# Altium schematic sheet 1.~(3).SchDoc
size 420 x 297 mm
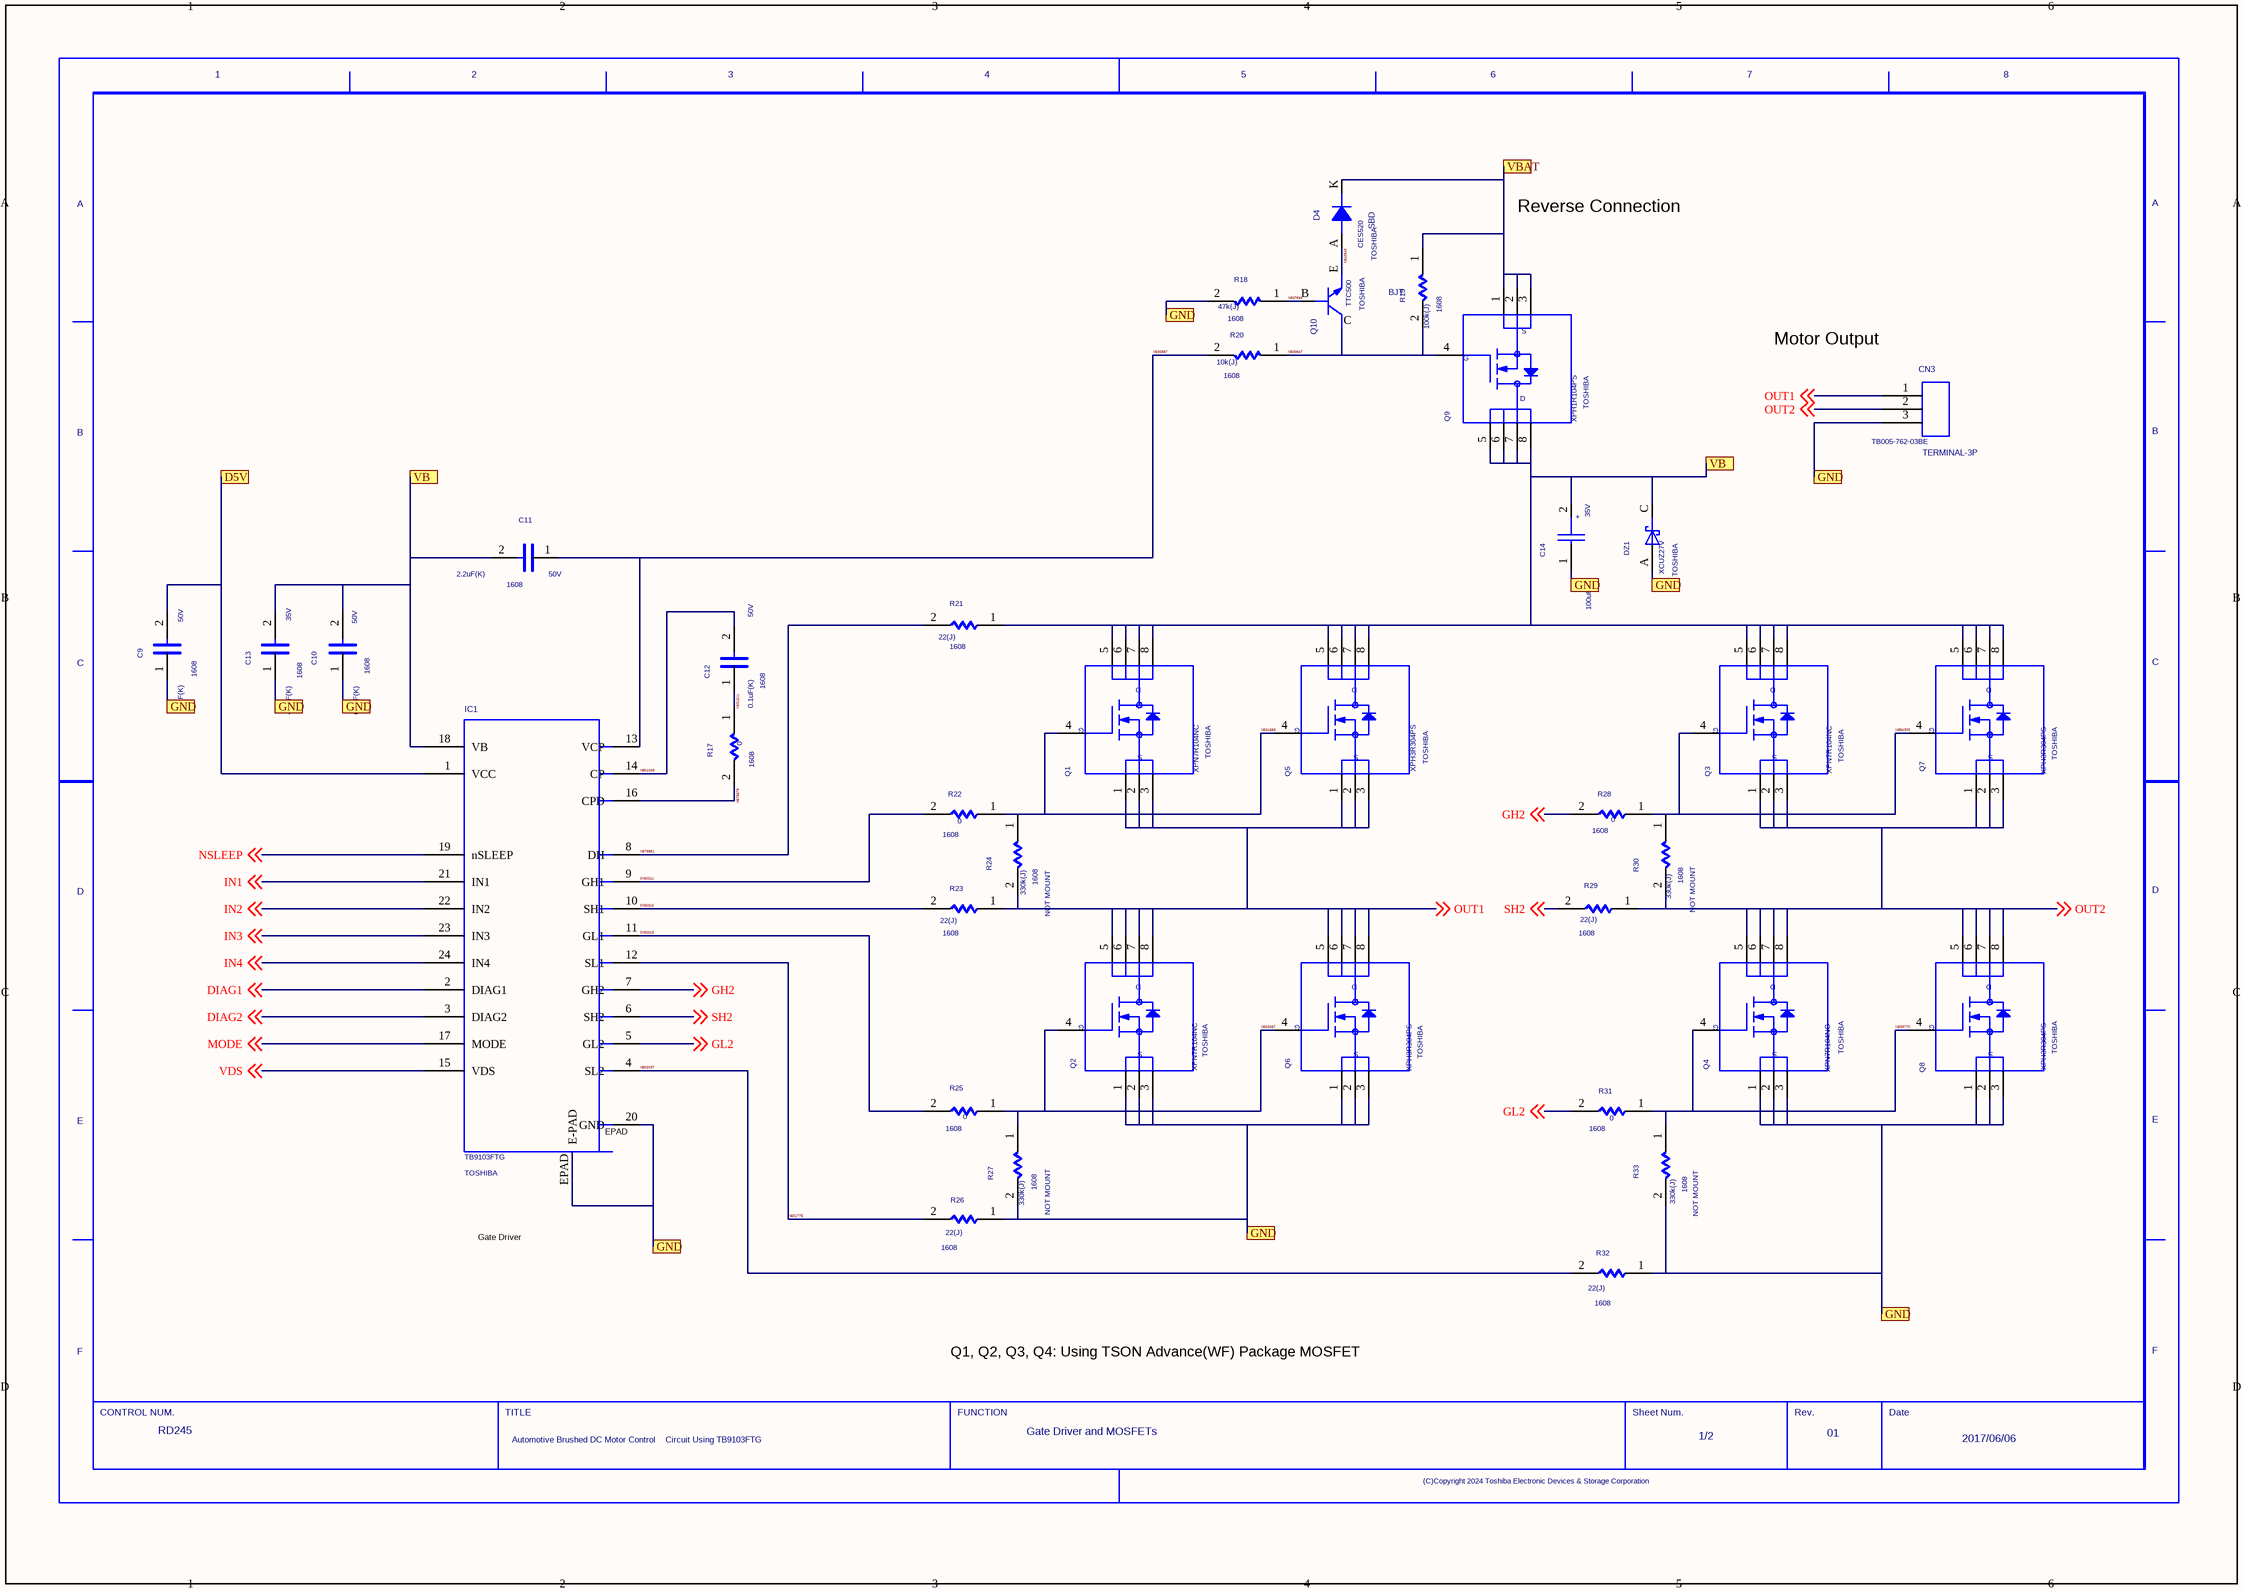
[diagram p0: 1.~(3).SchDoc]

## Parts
C9  SIZECODESMD: 1608  VAL2: 50V  VAL1: 0.1uF(K)  (hidden comment: C)
C10  SIZECODESMD: 1608  VAL2: 50V  VAL1: 0.1uF(K)  (hidden comment: C)
C11  SIZECODESMD: 1608  VAL2: 50V  VAL1: 2.2uF(K)  (hidden comment: C)
C12  SIZECODESMD: 1608  VAL2: 50V  VAL1: 0.1uF(K)  (hidden comment: C)
C13  SIZECODESMD: 1608  VAL2: 35V  VAL1: 4.7uF(K)  (hidden comment: C)
C14  VAL2: 35V  VAL1: 100uF(M)  (hidden comment: CP)
CN3  TERMINAL-3P  VAL3: TB005-762-03BE
D4  SBD  USERCOMPTEXT3: TOSHIBA  VAL3: CES520
DZ1  VAL3: XCUZ27V  USERCOMPTEXT3: TOSHIBA  (hidden comment: SBD)
IC1  USERCOMPTEXT3: TOSHIBA  VAL3: TB9103FTG  (hidden comment: TC241_3)
Q1  VAL3: XPN7R104NC  USERCOMPTEXT3: TOSHIBA  (hidden comment: MFNAC)
Q2  VAL3: XPN7R104NC  USERCOMPTEXT3: TOSHIBA  (hidden comment: MFNAC)
Q3  VAL3: XPN7R104NC  USERCOMPTEXT3: TOSHIBA  (hidden comment: MFNAC)
Q4  VAL3: XPN7R104NC  USERCOMPTEXT3: TOSHIBA  (hidden comment: MFNAC)
Q5  VAL3: XPH3R304PS  USERCOMPTEXT3: TOSHIBA  (hidden comment: MFNAC)
Q6  VAL3: XPH3R304PS  USERCOMPTEXT3: TOSHIBA  (hidden comment: MFNAC)
Q7  VAL3: XPH3R304PS  USERCOMPTEXT3: TOSHIBA  (hidden comment: MFNAC)
Q8  VAL3: XPH3R304PS  USERCOMPTEXT3: TOSHIBA  (hidden comment: MFNAC)
Q9  VAL3: XPH1R104PS  USERCOMPTEXT3: TOSHIBA  (hidden comment: MFNAC)
Q10  BJT  USERCOMPTEXT3: TOSHIBA  VAL3: TTC500
R17  SIZECODESMD: 1608  VAL1: 0  (hidden comment: R)
R18  SIZECODESMD: 1608  VAL1: 47k(J)  (hidden comment: R)
R19  SIZECODESMD: 1608  VAL1: 100k(J)  (hidden comment: R)
R20  SIZECODESMD: 1608  VAL1: 10k(J)  (hidden comment: R)
R21  SIZECODESMD: 1608  VAL1: 22(J)  (hidden comment: R)
R22  SIZECODESMD: 1608  VAL1: 0  (hidden comment: R)
R23  SIZECODESMD: 1608  VAL1: 22(J)  (hidden comment: R)
R24  SIZECODESMD: 1608  VAL1: 330k(J)  NOTMOUNT: NOT MOUNT  (hidden comment: R)
R25  SIZECODESMD: 1608  VAL1: 0  (hidden comment: R)
R26  SIZECODESMD: 1608  VAL1: 22(J)  (hidden comment: R)
R27  SIZECODESMD: 1608  VAL1: 330k(J)  NOTMOUNT: NOT MOUNT  (hidden comment: R)
R28  SIZECODESMD: 1608  VAL1: 0  (hidden comment: R)
R29  SIZECODESMD: 1608  VAL1: 22(J)  (hidden comment: R)
R30  SIZECODESMD: 1608  VAL1: 330k(J)  NOTMOUNT: NOT MOUNT  (hidden comment: R)
R31  SIZECODESMD: 1608  VAL1: 0  (hidden comment: R)
R32  SIZECODESMD: 1608  VAL1: 22(J)  (hidden comment: R)
R33  SIZECODESMD: 1608  VAL1: 330k(J)  NOTMOUNT: NOT MOUNT  (hidden comment: R)
U?  DATE: 2017/06/06  REVISION: 01  FUNCTION: Gate Driver and MOSFETs  DRAWINGNUMBER: RD245  TITLE: Automotive Brushed DC Motor Control / Circuit Using TB9103FTG  SHEETNUMBER: 1/2  (hidden comment: WAKU_DEF100)

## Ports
D5V, GND, VB, VBAT

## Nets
D5V: C9.2 IC1.1(VCC) ; port D5V
DIAG1: IC1.2(DIAG1) ; off-sheet DIAG1
DIAG2: IC1.3(DIAG2) ; off-sheet DIAG2
GH2: IC1.7(GH2) R28.2 ; off-sheet GH2
GL2: IC1.5(GL2) R31.2 ; off-sheet GL2
GND: C9.1 C10.1 C13.1 C14.1 CN3.3 DZ1.A IC1.20(GND) IC1.EPAD(E-PAD) Q2.1 Q2.2 Q2.3 Q4.1 Q4.2 Q4.3 Q6.1 Q6.2 Q6.3 Q8.1 Q8.2 Q8.3 R18.2 R26.1 R27.2 R32.1 R33.2 ; port GND
IN1: IC1.21(IN1) ; off-sheet IN1
IN2: IC1.22(IN2) ; off-sheet IN2
IN3: IC1.23(IN3) ; off-sheet IN3
IN4: IC1.24(IN4) ; off-sheet IN4
MODE: IC1.17(MODE) ; off-sheet MODE
N500947: Q9.4 Q10.C R19.2 R20.1
N500987: C11.1 IC1.13(VCP) R20.2
N501039: C12.2 IC1.14(CP)
N501211: C12.1 R17.1
N501689: Q1.4 Q5.4 R22.1 R24.1
N501775: IC1.12(SL1) R26.2
N502037: IC1.4(SL2) R32.2
N502087: Q2.4 Q6.4 R25.1 R27.1
N533770: Q4.4 Q8.4 R31.1 R33.1
N554303: Q3.4 Q7.4 R28.1 R30.1
N575579: IC1.16(CPD) R17.2
N576851: IC1.8(DH) R21.2
N607694: Q10.B R18.1
N610543: D4.A Q10.E
NSLEEP: IC1.19(nSLEEP) ; off-sheet NSLEEP
OUT1: CN3.1 Q1.1 Q1.2 Q1.3 Q2.5 Q2.6 Q2.7 Q2.8 Q5.1 Q5.2 Q5.3 Q6.5 Q6.6 Q6.7 Q6.8 R23.1 R24.2 ; off-sheet OUT1
OUT2: CN3.2 Q3.1 Q3.2 Q3.3 Q4.5 Q4.6 Q4.7 Q4.8 Q7.1 Q7.2 Q7.3 Q8.5 Q8.6 Q8.7 Q8.8 R29.1 R30.2 ; off-sheet OUT2
SH2: IC1.6(SH2) R29.2 ; off-sheet SH2
SIG0011: IC1.9(GH1) R22.2
SIG0012: IC1.10(SH1) R23.2
SIG0013: IC1.11(GL1) R25.2
VB: C10.2 C11.2 C13.2 C14.2 DZ1.C IC1.18(VB) Q1.5 Q1.6 Q1.7 Q1.8 Q3.5 Q3.6 Q3.7 Q3.8 Q5.5 Q5.6 Q5.7 Q5.8 Q7.5 Q7.6 Q7.7 Q7.8 Q9.5 Q9.6 Q9.7 Q9.8 R21.1 ; port VB
VBAT: D4.K Q9.1 Q9.2 Q9.3 R19.1 ; port VBAT
VDS: IC1.15(VDS) ; off-sheet VDS

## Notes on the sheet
- Reverse Connection
  Protector
- Motor Output
- (near IC1) EPAD
- Gate Driver
- Q1, Q2, Q3, Q4: Using TSON Advance(WF) Package MOSFET
  Q5, Q6, Q7, Q8: Using SOP Advance(WF) Package MOSFET

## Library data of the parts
C9 = C: UPDATETIME: 17:22:43; UPDATEUSER: sptcae13; SAVECOUNT: 1; ORIGINALSYMBOLORIGIN: (0,0); QUADMODEL: CON_10U; FUNCN: C_C; NOMINALCAPACITA: 10u; RATEDVOLTAGE: 25; CDMASTERCADCELG: KC0167; MAKER: TDK; OUMEMAKER: MRT 村田製作所; ADSMODELNAME: s_ZRB18AR61E106ME01L; VAL4: Murata; FNLEADFREETHET1GT2GMCTH1: N_N_N; VAL3: GCM188R71H104KA57J; CAPACITANCETOLE: M; OUMECLASSIFICATION: セラミックコンデンサ; OUMEMAKERKATAMEI: ZRB18AR61E106ME01L; INSTANCENAME: INS530329
C10 = C: UPDATETIME: 17:22:43; UPDATEUSER: sptcae13; SAVECOUNT: 1; ORIGINALSYMBOLORIGIN: (0,0); QUADMODEL: CON_10U; FUNCN: C_C; NOMINALCAPACITA: 10u; RATEDVOLTAGE: 25; CDMASTERCADCELG: KC0167; MAKER: TDK; OUMEMAKER: MRT 村田製作所; ADSMODELNAME: s_ZRB18AR61E106ME01L; VAL4: Murata; FNLEADFREETHET1GT2GMCTH1: N_N_N; VAL3: GCM188R71H104KA57J; CAPACITANCETOLE: M; OUMECLASSIFICATION: セラミックコンデンサ; OUMEMAKERKATAMEI: ZRB18AR61E106ME01L; INSTANCENAME: INS530425
C11 = C: UPDATETIME: 17:22:43; UPDATEUSER: sptcae13; SAVECOUNT: 1; ORIGINALSYMBOLORIGIN: (0,0); QUADMODEL: CON_10U; FUNCN: C_C; NOMINALCAPACITA: 10u; RATEDVOLTAGE: 25; CDMASTERCADCELG: KC0167; MAKER: TDK; OUMEMAKER: MRT 村田製作所; ADSMODELNAME: s_ZRB18AR61E106ME01L; VAL4: Murata; FNLEADFREETHET1GT2GMCTH1: N_N_N; VAL3: GRT188R61H225KE13D; CAPACITANCETOLE: M; OUMECLASSIFICATION: セラミックコンデンサ; OUMEMAKERKATAMEI: ZRB18AR61E106ME01L; INSTANCENAME: INS530173
C12 = C: UPDATETIME: 17:22:43; UPDATEUSER: sptcae13; SAVECOUNT: 1; ORIGINALSYMBOLORIGIN: (0,0); QUADMODEL: CON_10U; FUNCN: C_C; NOMINALCAPACITA: 10u; RATEDVOLTAGE: 25; CDMASTERCADCELG: KC0167; MAKER: TDK; OUMEMAKER: MRT 村田製作所; ADSMODELNAME: s_ZRB18AR61E106ME01L; VAL4: Murata; FNLEADFREETHET1GT2GMCTH1: N_N_N; VAL3: GCM188R71H104KA57J; CAPACITANCETOLE: M; OUMECLASSIFICATION: セラミックコンデンサ; OUMEMAKERKATAMEI: ZRB18AR61E106ME01L; INSTANCENAME: INS529943
C13 = C: UPDATETIME: 17:22:43; UPDATEUSER: sptcae13; SAVECOUNT: 1; ORIGINALSYMBOLORIGIN: (0,0); QUADMODEL: CON_10U; FUNCN: C_C; NOMINALCAPACITA: 10u; RATEDVOLTAGE: 25; CDMASTERCADCELG: KC0167; MAKER: TDK; OUMEMAKER: MRT 村田製作所; ADSMODELNAME: s_ZRB18AR61E106ME01L; VAL4: Murata; FNLEADFREETHET1GT2GMCTH1: N_N_N; VAL3: GRT188R6YA475KE13D; CAPACITANCETOLE: M; OUMECLASSIFICATION: セラミックコンデンサ; OUMEMAKERKATAMEI: ZRB18AR61E106ME01L; INSTANCENAME: INS647841
C14 = CP: OUMEPARTTYPE: C; SAVEAREA0: -1450,-153,20294,13055; UPDATETIME: 16:13:42; UPDATEUSER: fukuda-y; TIME: 15:02:55; SAVECOUNT: 52; ORIGINALSYMBOLORIGIN: (0,0); QUADMODEL: CON_330U; FUNCN: CP_CP; RATEDVOLTAGE: 450; NOMINALCAPACITA: 330u; CDMASTERCADCELG: DC213N; MAKER: RUBYCON; GCOUNT: 1; SIZECODESMD: DIP; OUMEMAKER: SIT ルビコン; VAL4: Chemi-Con; FNLEADFREETHET1GT2GMCTH1: 9_N_N; VAL3: HHXD350ARA101MHA0G; CAPACITANCETOLE: M; OUMECLASSIFICATION: アルミ電解コンデンサ; OUMEMAKERKATAMEI: 450MXC330M35X40; CHIPSIZE: D35xL30; INSTANCENAME: INS636800
CN3 = CON3: SAVECOUNT: 1; UPDATEUSER: sptcae13; UPDATETIME: 09:49:24; OriginalSymbolOrigin: (0,0); FUNCN: CON3_CON3; VAL4: CUI Devices; VAL2: 300V/30A; INSTANCENAME: INS530345
D4 = DIODE_0: SAVECOUNT: 1; UPDATEUSER: sptcae13; UPDATETIME: 09:49:24; OriginalSymbolOrigin: (0,0); FUNCN: DIODE_0_DIODE_0; INSTANCENAME: INS530245
DZ1 = SBD: SAVEAREA0: -4630,-153,17114,13055; UPDATETIME: 08:16:22; UPDATEUSER: fukuda-y; TIME: 14:49:55; SAVECOUNT: 1; ORIGINALSYMBOLORIGIN: (0,0); COMPONENTNAME: SBD_SBD; INSTANCENAME: INS530189
IC1 = TC241_3: SAVECOUNT: 1; UPDATEUSER: sptcae13; UPDATETIME: 09:49:24; OriginalSymbolOrigin: (0,0); FUNCN: TC241_3_Graphic_Schematic_1_package; VAL1: GATE_DRIVER; INSTANCENAME: cmp65
Q1 = MFNAC_23: SAVEAREA0: -10143,-336,37609,28718; UPDATETIME: 14:45:16; UPDATEUSER: 19990028; TIME: 18:29:30; SAVECOUNT: 1; ORIGINALSYMBOLORIGIN: (0,0); COMPONENTNAME: MFNAC_23_MFNAC_23; INSTANCENAME: INS529903
Q2 = MFNAC_23: SAVEAREA0: -10143,-336,37609,28718; UPDATETIME: 14:45:16; UPDATEUSER: 19990028; TIME: 18:29:30; SAVECOUNT: 1; ORIGINALSYMBOLORIGIN: (0,0); COMPONENTNAME: MFNAC_23_MFNAC_23; INSTANCENAME: INS530205
Q3 = MFNAC_23: SAVEAREA0: -10143,-336,37609,28718; UPDATETIME: 14:45:16; UPDATEUSER: 19990028; TIME: 18:29:30; SAVECOUNT: 1; ORIGINALSYMBOLORIGIN: (0,0); COMPONENTNAME: MFNAC_23_MFNAC_23; INSTANCENAME: INS533486
Q4 = MFNAC_23: SAVEAREA0: -10143,-336,37609,28718; UPDATETIME: 14:45:16; UPDATEUSER: 19990028; TIME: 18:29:30; SAVECOUNT: 1; ORIGINALSYMBOLORIGIN: (0,0); COMPONENTNAME: MFNAC_23_MFNAC_23; INSTANCENAME: INS533696
Q5 = MFNAC_23: SAVEAREA0: -10143,-336,37609,28718; UPDATETIME: 14:45:16; UPDATEUSER: 19990028; TIME: 18:29:30; SAVECOUNT: 1; ORIGINALSYMBOLORIGIN: (0,0); COMPONENTNAME: MFNAC_23_MFNAC_23; INSTANCENAME: INS530025
Q6 = MFNAC_23: SAVEAREA0: -10143,-336,37609,28718; UPDATETIME: 14:45:16; UPDATEUSER: 19990028; TIME: 18:29:30; SAVECOUNT: 1; ORIGINALSYMBOLORIGIN: (0,0); COMPONENTNAME: MFNAC_23_MFNAC_23; INSTANCENAME: INS530385
Q7 = MFNAC_23: SAVEAREA0: -10143,-336,37609,28718; UPDATETIME: 14:45:16; UPDATEUSER: 19990028; TIME: 18:29:30; SAVECOUNT: 1; ORIGINALSYMBOLORIGIN: (0,0); COMPONENTNAME: MFNAC_23_MFNAC_23; INSTANCENAME: INS533510
Q8 = MFNAC_23: SAVEAREA0: -10143,-336,37609,28718; UPDATETIME: 14:45:16; UPDATEUSER: 19990028; TIME: 18:29:30; SAVECOUNT: 1; ORIGINALSYMBOLORIGIN: (0,0); COMPONENTNAME: MFNAC_23_MFNAC_23; INSTANCENAME: INS533720
Q9 = MFNAC_23: SAVEAREA0: -10143,-336,37609,28718; UPDATETIME: 14:45:16; UPDATEUSER: 19990028; TIME: 18:29:30; SAVECOUNT: 1; ORIGINALSYMBOLORIGIN: (0,0); COMPONENTNAME: MFNAC_23_MFNAC_23; INSTANCENAME: INS529983
Q10 = 2N1069_0: SAVECOUNT: 1; UPDATEUSER: sptcae13; UPDATETIME: 09:49:24; PSPICETEMPLATE: Q^@REFDES %C %B %E; OriginalSymbolOrigin: (0,5080); FUNCN: 2N1069_0_2N1069_0; INSTANCENAME: INS529959
R17 = R: UPDATETIME: 17:22:43; UPDATEUSER: sptcae13; SAVECOUNT: 1; ORIGINALSYMBOLORIGIN: (0,0); QUADMODEL: RES_1M; FUNCN: R_R; CDMASTERCADCELG: KC0020; MAKER: KOA; RESISTANCETOLER: J; OUMEMAKER: SSM 進工業; POWERRATING: 500m; MOUNTINGFORMSMD: SMD; NOMINALRESISTAN: 1m; ADSMODELNAME: s_RL1632H_R001_JN; FNLEADFREETHET1GT2GMCTH1: N_N_N; VAL3: RK73Z1JTTD; OUMECLASSIFICATION: 表面実装用固定抵抗器; OUMEMAKERKATAMEI: RL1632H-R001-JN; CHIPSIZE: 3216; INSTANCENAME: INS529855
R18 = R: UPDATETIME: 17:22:43; UPDATEUSER: sptcae13; SAVECOUNT: 1; ORIGINALSYMBOLORIGIN: (0,0); QUADMODEL: RES_1M; FUNCN: R_R; CDMASTERCADCELG: KC0020; MAKER: KOA; RESISTANCETOLER: J; OUMEMAKER: SSM 進工業; POWERRATING: 500m; MOUNTINGFORMSMD: SMD; NOMINALRESISTAN: 1m; ADSMODELNAME: s_RL1632H_R001_JN; FNLEADFREETHET1GT2GMCTH1: N_N_N; VAL3: RK73B1JTTD473J; VAL2: 100mW; OUMECLASSIFICATION: 表面実装用固定抵抗器; OUMEMAKERKATAMEI: RL1632H-R001-JN; CHIPSIZE: 3216; INSTANCENAME: INS529871
R19 = R: UPDATETIME: 17:22:43; UPDATEUSER: sptcae13; SAVECOUNT: 1; ORIGINALSYMBOLORIGIN: (0,0); QUADMODEL: RES_1M; FUNCN: R_R; CDMASTERCADCELG: KC0020; MAKER: KOA; RESISTANCETOLER: J; OUMEMAKER: SSM 進工業; POWERRATING: 500m; MOUNTINGFORMSMD: SMD; NOMINALRESISTAN: 1m; ADSMODELNAME: s_RL1632H_R001_JN; FNLEADFREETHET1GT2GMCTH1: N_N_N; VAL3: RK73B1JTTD104J; VAL2: 100mW; OUMECLASSIFICATION: 表面実装用固定抵抗器; OUMEMAKERKATAMEI: RL1632H-R001-JN; CHIPSIZE: 3216; INSTANCENAME: INS530265
R20 = R: UPDATETIME: 17:22:43; UPDATEUSER: sptcae13; SAVECOUNT: 1; ORIGINALSYMBOLORIGIN: (0,0); QUADMODEL: RES_1M; FUNCN: R_R; CDMASTERCADCELG: KC0020; MAKER: KOA; RESISTANCETOLER: J; OUMEMAKER: SSM 進工業; POWERRATING: 500m; MOUNTINGFORMSMD: SMD; NOMINALRESISTAN: 1m; ADSMODELNAME: s_RL1632H_R001_JN; FNLEADFREETHET1GT2GMCTH1: N_N_N; VAL3: RK73B1JTTD103J; VAL2: 100mW; OUMECLASSIFICATION: 表面実装用固定抵抗器; OUMEMAKERKATAMEI: RL1632H-R001-JN; CHIPSIZE: 3216; INSTANCENAME: INS529887
R21 = R: UPDATETIME: 17:22:43; UPDATEUSER: sptcae13; SAVECOUNT: 1; ORIGINALSYMBOLORIGIN: (0,0); QUADMODEL: RES_1M; FUNCN: R_R; CDMASTERCADCELG: KC0020; MAKER: KOA; RESISTANCETOLER: J; OUMEMAKER: SSM 進工業; POWERRATING: 500m; MOUNTINGFORMSMD: SMD; NOMINALRESISTAN: 1m; ADSMODELNAME: s_RL1632H_R001_JN; FNLEADFREETHET1GT2GMCTH1: N_N_N; VAL3: RK73B1JTTD220J; VAL2: 125mW; OUMECLASSIFICATION: 表面実装用固定抵抗器; OUMEMAKERKATAMEI: RL1632H-R001-JN; CHIPSIZE: 3216; INSTANCENAME: INS575614
R22 = R: UPDATETIME: 17:22:43; UPDATEUSER: sptcae13; SAVECOUNT: 1; ORIGINALSYMBOLORIGIN: (0,0); QUADMODEL: RES_1M; FUNCN: R_R; CDMASTERCADCELG: KC0020; MAKER: KOA; RESISTANCETOLER: J; OUMEMAKER: SSM 進工業; POWERRATING: 500m; MOUNTINGFORMSMD: SMD; NOMINALRESISTAN: 1m; ADSMODELNAME: s_RL1632H_R001_JN; FNLEADFREETHET1GT2GMCTH1: N_N_N; VAL3: RK73Z1JTTD; OUMECLASSIFICATION: 表面実装用固定抵抗器; OUMEMAKERKATAMEI: RL1632H-R001-JN; CHIPSIZE: 3216; INSTANCENAME: INS530281
R23 = R: UPDATETIME: 17:22:43; UPDATEUSER: sptcae13; SAVECOUNT: 1; ORIGINALSYMBOLORIGIN: (0,0); QUADMODEL: RES_1M; FUNCN: R_R; CDMASTERCADCELG: KC0020; MAKER: KOA; RESISTANCETOLER: J; OUMEMAKER: SSM 進工業; POWERRATING: 500m; MOUNTINGFORMSMD: SMD; NOMINALRESISTAN: 1m; ADSMODELNAME: s_RL1632H_R001_JN; FNLEADFREETHET1GT2GMCTH1: N_N_N; VAL3: RK73B1JTTD220J; VAL2: 125mW; OUMECLASSIFICATION: 表面実装用固定抵抗器; OUMEMAKERKATAMEI: RL1632H-R001-JN; CHIPSIZE: 3216; INSTANCENAME: INS577102
R24 = R: UPDATETIME: 17:22:43; UPDATEUSER: sptcae13; SAVECOUNT: 1; ORIGINALSYMBOLORIGIN: (0,0); QUADMODEL: RES_1M; FUNCN: R_R; CDMASTERCADCELG: KC0020; MAKER: KOA; RESISTANCETOLER: J; OUMEMAKER: SSM 進工業; POWERRATING: 500m; MOUNTINGFORMSMD: SMD; NOMINALRESISTAN: 1m; ADSMODELNAME: s_RL1632H_R001_JN; FNLEADFREETHET1GT2GMCTH1: N_N_N; VAL3: RK73B1JTTD334J; VAL2: 100mW; OUMECLASSIFICATION: 表面実装用固定抵抗器; OUMEMAKERKATAMEI: RL1632H-R001-JN; CHIPSIZE: 3216; INSTANCENAME: INS586735
R25 = R: UPDATETIME: 17:22:43; UPDATEUSER: sptcae13; SAVECOUNT: 1; ORIGINALSYMBOLORIGIN: (0,0); QUADMODEL: RES_1M; FUNCN: R_R; CDMASTERCADCELG: KC0020; MAKER: KOA; RESISTANCETOLER: J; OUMEMAKER: SSM 進工業; POWERRATING: 500m; MOUNTINGFORMSMD: SMD; NOMINALRESISTAN: 1m; ADSMODELNAME: s_RL1632H_R001_JN; FNLEADFREETHET1GT2GMCTH1: N_N_N; VAL3: RK73Z1JTTD; OUMECLASSIFICATION: 表面実装用固定抵抗器; OUMEMAKERKATAMEI: RL1632H-R001-JN; CHIPSIZE: 3216; INSTANCENAME: INS530297
R26 = R: UPDATETIME: 17:22:43; UPDATEUSER: sptcae13; SAVECOUNT: 1; ORIGINALSYMBOLORIGIN: (0,0); QUADMODEL: RES_1M; FUNCN: R_R; CDMASTERCADCELG: KC0020; MAKER: KOA; RESISTANCETOLER: J; OUMEMAKER: SSM 進工業; POWERRATING: 500m; MOUNTINGFORMSMD: SMD; NOMINALRESISTAN: 1m; ADSMODELNAME: s_RL1632H_R001_JN; FNLEADFREETHET1GT2GMCTH1: N_N_N; VAL3: RK73B1JTTD220J; VAL2: 125mW; OUMECLASSIFICATION: 表面実装用固定抵抗器; OUMEMAKERKATAMEI: RL1632H-R001-JN; CHIPSIZE: 3216; INSTANCENAME: INS577602
R27 = R: UPDATETIME: 17:22:43; UPDATEUSER: sptcae13; SAVECOUNT: 1; ORIGINALSYMBOLORIGIN: (0,0); QUADMODEL: RES_1M; FUNCN: R_R; CDMASTERCADCELG: KC0020; MAKER: KOA; RESISTANCETOLER: J; OUMEMAKER: SSM 進工業; POWERRATING: 500m; MOUNTINGFORMSMD: SMD; NOMINALRESISTAN: 1m; ADSMODELNAME: s_RL1632H_R001_JN; FNLEADFREETHET1GT2GMCTH1: N_N_N; VAL3: RK73B1JTTD334J; VAL2: 100mW; OUMECLASSIFICATION: 表面実装用固定抵抗器; OUMEMAKERKATAMEI: RL1632H-R001-JN; CHIPSIZE: 3216; INSTANCENAME: INS591774
R28 = R: UPDATETIME: 17:22:43; UPDATEUSER: sptcae13; SAVECOUNT: 1; ORIGINALSYMBOLORIGIN: (0,0); QUADMODEL: RES_1M; FUNCN: R_R; CDMASTERCADCELG: KC0020; MAKER: KOA; RESISTANCETOLER: J; OUMEMAKER: SSM 進工業; POWERRATING: 500m; MOUNTINGFORMSMD: SMD; NOMINALRESISTAN: 1m; ADSMODELNAME: s_RL1632H_R001_JN; FNLEADFREETHET1GT2GMCTH1: N_N_N; VAL3: RK73Z1JTTD; OUMECLASSIFICATION: 表面実装用固定抵抗器; OUMEMAKERKATAMEI: RL1632H-R001-JN; CHIPSIZE: 3216; INSTANCENAME: INS533534
R29 = R: UPDATETIME: 17:22:43; UPDATEUSER: sptcae13; SAVECOUNT: 1; ORIGINALSYMBOLORIGIN: (0,0); QUADMODEL: RES_1M; FUNCN: R_R; CDMASTERCADCELG: KC0020; MAKER: KOA; RESISTANCETOLER: J; OUMEMAKER: SSM 進工業; POWERRATING: 500m; MOUNTINGFORMSMD: SMD; NOMINALRESISTAN: 1m; ADSMODELNAME: s_RL1632H_R001_JN; FNLEADFREETHET1GT2GMCTH1: N_N_N; VAL3: RK73B1JTTD220J; VAL2: 125mW; OUMECLASSIFICATION: 表面実装用固定抵抗器; OUMEMAKERKATAMEI: RL1632H-R001-JN; CHIPSIZE: 3216; INSTANCENAME: INS579870
R30 = R: UPDATETIME: 17:22:43; UPDATEUSER: sptcae13; SAVECOUNT: 1; ORIGINALSYMBOLORIGIN: (0,0); QUADMODEL: RES_1M; FUNCN: R_R; CDMASTERCADCELG: KC0020; MAKER: KOA; RESISTANCETOLER: J; OUMEMAKER: SSM 進工業; POWERRATING: 500m; MOUNTINGFORMSMD: SMD; NOMINALRESISTAN: 1m; ADSMODELNAME: s_RL1632H_R001_JN; FNLEADFREETHET1GT2GMCTH1: N_N_N; VAL3: RK73B1JTTD334J; VAL2: 100mW; OUMECLASSIFICATION: 表面実装用固定抵抗器; OUMEMAKERKATAMEI: RL1632H-R001-JN; CHIPSIZE: 3216; INSTANCENAME: INS592756
R31 = R: UPDATETIME: 17:22:43; UPDATEUSER: sptcae13; SAVECOUNT: 1; ORIGINALSYMBOLORIGIN: (0,0); QUADMODEL: RES_1M; FUNCN: R_R; CDMASTERCADCELG: KC0020; MAKER: KOA; RESISTANCETOLER: J; OUMEMAKER: SSM 進工業; POWERRATING: 500m; MOUNTINGFORMSMD: SMD; NOMINALRESISTAN: 1m; ADSMODELNAME: s_RL1632H_R001_JN; FNLEADFREETHET1GT2GMCTH1: N_N_N; VAL3: RK73Z1JTTD; OUMECLASSIFICATION: 表面実装用固定抵抗器; OUMEMAKERKATAMEI: RL1632H-R001-JN; CHIPSIZE: 3216; INSTANCENAME: INS533744
R32 = R: UPDATETIME: 17:22:43; UPDATEUSER: sptcae13; SAVECOUNT: 1; ORIGINALSYMBOLORIGIN: (0,0); QUADMODEL: RES_1M; FUNCN: R_R; CDMASTERCADCELG: KC0020; MAKER: KOA; RESISTANCETOLER: J; OUMEMAKER: SSM 進工業; POWERRATING: 500m; MOUNTINGFORMSMD: SMD; NOMINALRESISTAN: 1m; ADSMODELNAME: s_RL1632H_R001_JN; FNLEADFREETHET1GT2GMCTH1: N_N_N; VAL3: RK73B1JTTD220J; VAL2: 125mW; OUMECLASSIFICATION: 表面実装用固定抵抗器; OUMEMAKERKATAMEI: RL1632H-R001-JN; CHIPSIZE: 3216; INSTANCENAME: INS577624
R33 = R: UPDATETIME: 17:22:43; UPDATEUSER: sptcae13; SAVECOUNT: 1; ORIGINALSYMBOLORIGIN: (0,0); QUADMODEL: RES_1M; FUNCN: R_R; CDMASTERCADCELG: KC0020; MAKER: KOA; RESISTANCETOLER: J; OUMEMAKER: SSM 進工業; POWERRATING: 500m; MOUNTINGFORMSMD: SMD; NOMINALRESISTAN: 1m; ADSMODELNAME: s_RL1632H_R001_JN; FNLEADFREETHET1GT2GMCTH1: N_N_N; VAL3: RK73B1JTTD334J; VAL2: 100mW; OUMECLASSIFICATION: 表面実装用固定抵抗器; OUMEMAKERKATAMEI: RL1632H-R001-JN; CHIPSIZE: 3216; INSTANCENAME: INS592511
U? = WAKU_DEF100_1: SAVECOUNT: 1; UPDATEUSER: sptcae09; UPDATETIME: 10:40:02; PLOTTIME: HH:MM; TIME: 09:49:24; SAVEAREA0: -63393,-16950,474261,314592; ORIGINALSYMBOLORIGIN: (0,0); PAGENUMBER: 8; DESIGNED: TOSHIBA; SHTSAVECOUNT: 37; INSTANCENAME: INS636826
